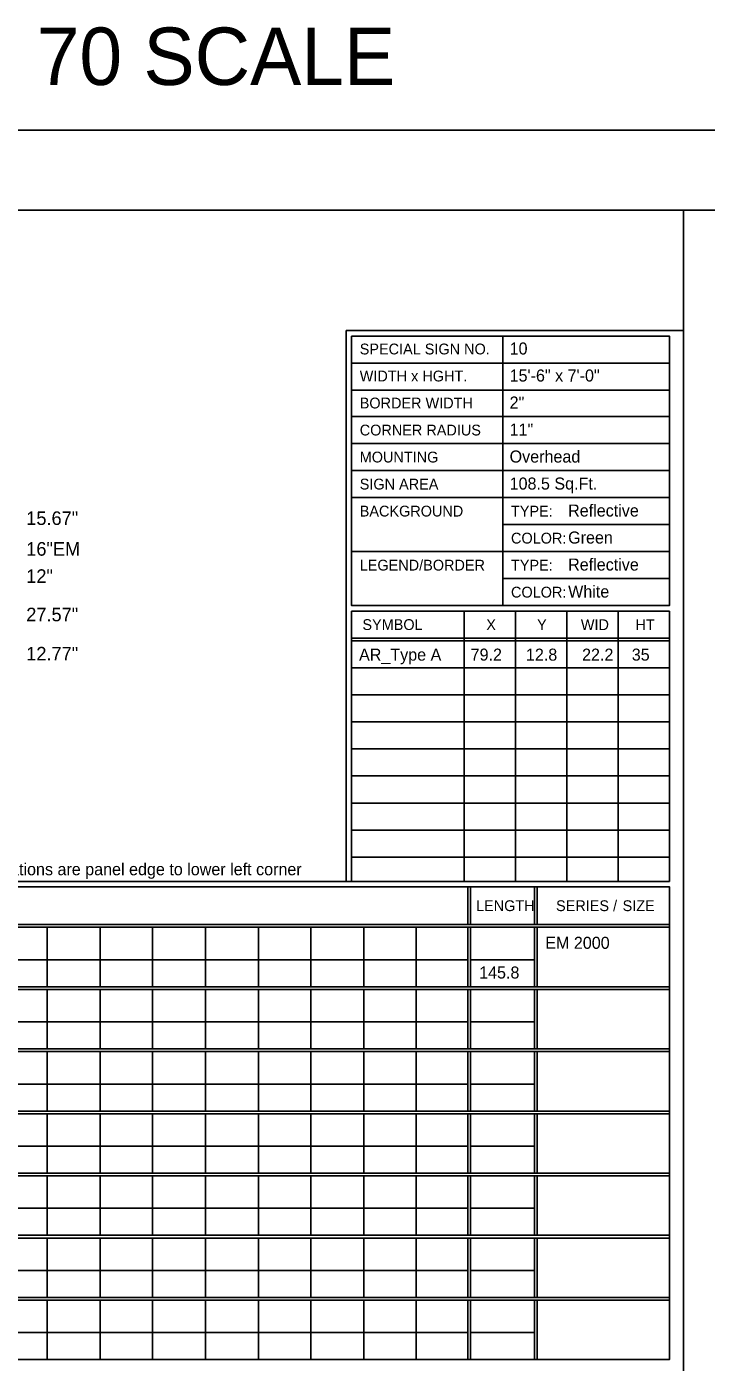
# Model space of a CAD drawing. Extents: x 2150010 to 2150174, y 145114 to 145224.
# Drawn here: x 2150107.3 to 2150136.4, y 145167.1 to 145224.4 of the extents above; entities that cross this region are included whole.
import ezdxf

# ---------------------------------------------------------------- set-up
doc = ezdxf.new("R2010")
doc.units = 0
for name, color, linetype in [('BORDER', 7, 'Continuous'), ('GSDIMS', 7, 'Continuous'), ('GSSHT', 7, 'Continuous'), ('Level 1', 7, 'Continuous'), ('PDF', 7, 'Continuous'), ('TEXT', 7, 'Continuous')]:
    doc.layers.add(name, color=color, linetype=linetype)

msp = doc.modelspace()

# ---------------------------------------------------------------- linework, layer by layer
at = {"layer": 'BORDER'}
for p, q in [((2150010.458, 145219.948), (2150174.061, 145219.948)), ((2150171.536, 145216.512), (2150017.557, 145216.512))]:
    msp.add_line(p, q, dxfattribs=at)
at = {"layer": 'Level 1'}
for p, q in [((2150135.447, 145216.512), (2150135.447, 145124.606)), ((2150120.969, 145211.34), (2150135.447, 145211.34)), ((2150127.694, 145211.108), (2150127.694, 145199.537)), ((2150121.201, 145209.949), (2150134.843, 145209.949)), ((2150121.201, 145208.789), (2150134.843, 145208.789)), ((2150121.201, 145207.653), (2150134.843, 145207.653)), ((2150121.201, 145206.494), (2150134.843, 145206.494)), ((2150121.201, 145205.334), (2150134.843, 145205.334)), ((2150121.201, 145204.175), (2150134.843, 145204.175)), ((2150127.694, 145203.015), (2150134.843, 145203.015)), ((2150121.201, 145201.856), (2150134.843, 145201.856)), ((2150127.694, 145200.696), (2150134.843, 145200.696)), ((2150121.201, 145187.705), (2150121.201, 145199.305)), ((2150121.201, 145199.305), (2150134.843, 145199.305)), ((2150126.031, 145199.299), (2150126.031, 145198.14)), ((2150128.234, 145199.299), (2150128.234, 145198.14)), ((2150130.437, 145199.299), (2150130.437, 145198.14)), ((2150132.64, 145199.299), (2150132.64, 145198.14)), ((2150134.843, 145199.305), (2150134.843, 145187.705)), ((2150121.201, 145198.14), (2150134.843, 145198.14)), ((2150121.201, 145198.024), (2150134.843, 145198.024)), ((2150126.031, 145198.14), (2150126.031, 145187.705)), ((2150128.234, 145198.14), (2150128.234, 145187.705)), ((2150130.437, 145198.14), (2150130.437, 145187.705)), ((2150132.64, 145198.14), (2150132.64, 145187.705)), ((2150121.201, 145196.864), (2150134.843, 145196.864)), ((2150121.201, 145195.705), (2150134.843, 145195.705)), ((2150121.201, 145194.545), (2150134.843, 145194.545)), ((2150121.201, 145193.386), (2150134.843, 145193.386)), ((2150121.201, 145192.227), (2150134.843, 145192.227)), ((2150121.201, 145191.067), (2150134.843, 145191.067)), ((2150121.201, 145189.908), (2150134.843, 145189.908)), ((2150121.201, 145188.748), (2150134.843, 145188.748)), ((2150076.316, 145187.705), (2150121.342, 145187.705)), ((2150134.843, 145187.705), (2150121.201, 145187.705)), ((2150126.185, 145187.473), (2150126.185, 145185.849)), ((2150126.301, 145187.473), (2150126.301, 145185.849)), ((2150129.048, 145187.473), (2150129.048, 145185.849)), ((2150129.164, 145187.473), (2150129.164, 145185.849)), ((2150076.548, 145185.849), (2150134.843, 145185.849)), ((2150076.548, 145185.733), (2150134.843, 145185.733)), ((2150108.132, 145185.733), (2150108.132, 145183.183)), ((2150110.405, 145185.733), (2150110.405, 145183.183)), ((2150112.654, 145185.733), (2150112.654, 145183.183)), ((2150114.927, 145185.733), (2150114.927, 145183.183)), ((2150117.199, 145185.733), (2150117.199, 145183.183)), ((2150119.449, 145185.733), (2150119.449, 145183.183)), ((2150121.721, 145185.733), (2150121.721, 145183.183)), ((2150123.97, 145185.733), (2150123.97, 145183.183)), ((2150126.185, 145185.733), (2150126.185, 145183.183)), ((2150126.301, 145185.733), (2150126.301, 145183.183)), ((2150129.048, 145185.733), (2150129.048, 145183.183)), ((2150129.164, 145185.733), (2150129.164, 145183.183)), ((2150076.548, 145184.342), (2150126.185, 145184.342)), ((2150126.301, 145184.342), (2150129.048, 145184.342)), ((2150076.548, 145183.183), (2150134.843, 145183.183)), ((2150076.548, 145183.067), (2150134.843, 145183.067)), ((2150108.132, 145183.067), (2150108.132, 145180.516)), ((2150110.405, 145183.067), (2150110.405, 145180.516)), ((2150112.654, 145183.067), (2150112.654, 145180.516)), ((2150114.927, 145183.067), (2150114.927, 145180.516)), ((2150117.199, 145183.067), (2150117.199, 145180.516)), ((2150119.449, 145183.067), (2150119.449, 145180.516)), ((2150121.721, 145183.067), (2150121.721, 145180.516)), ((2150123.97, 145183.067), (2150123.97, 145180.516)), ((2150126.185, 145183.067), (2150126.185, 145180.516)), ((2150126.301, 145183.067), (2150126.301, 145180.516)), ((2150129.048, 145183.067), (2150129.048, 145180.516)), ((2150129.164, 145183.067), (2150129.164, 145180.516)), ((2150076.548, 145181.675), (2150126.185, 145181.675)), ((2150126.301, 145181.675), (2150129.048, 145181.675)), ((2150076.548, 145180.516), (2150134.843, 145180.516)), ((2150076.548, 145180.4), (2150134.843, 145180.4)), ((2150108.132, 145180.4), (2150108.132, 145177.849)), ((2150110.405, 145180.4), (2150110.405, 145177.849)), ((2150112.654, 145180.4), (2150112.654, 145177.849)), ((2150114.927, 145180.4), (2150114.927, 145177.849)), ((2150117.199, 145180.4), (2150117.199, 145177.849)), ((2150119.449, 145180.4), (2150119.449, 145177.849)), ((2150121.721, 145180.4), (2150121.721, 145177.849)), ((2150123.97, 145180.4), (2150123.97, 145177.849)), ((2150126.185, 145180.4), (2150126.185, 145177.849)), ((2150126.301, 145180.4), (2150126.301, 145177.849)), ((2150129.048, 145180.4), (2150129.048, 145177.849)), ((2150129.164, 145180.4), (2150129.164, 145177.849)), ((2150076.548, 145179.008), (2150126.185, 145179.008)), ((2150126.301, 145179.008), (2150129.048, 145179.008)), ((2150076.548, 145177.849), (2150134.843, 145177.849)), ((2150076.548, 145177.733), (2150134.843, 145177.733)), ((2150108.132, 145177.733), (2150108.132, 145175.182)), ((2150110.405, 145177.733), (2150110.405, 145175.182)), ((2150112.654, 145177.733), (2150112.654, 145175.182)), ((2150114.927, 145177.733), (2150114.927, 145175.182)), ((2150117.199, 145177.733), (2150117.199, 145175.182)), ((2150119.449, 145177.733), (2150119.449, 145175.182)), ((2150121.721, 145177.733), (2150121.721, 145175.182)), ((2150123.97, 145177.733), (2150123.97, 145175.182)), ((2150126.185, 145177.733), (2150126.185, 145175.182)), ((2150126.301, 145177.733), (2150126.301, 145175.182)), ((2150129.048, 145177.733), (2150129.048, 145175.182)), ((2150129.164, 145177.733), (2150129.164, 145175.182)), ((2150076.548, 145176.342), (2150126.185, 145176.342)), ((2150126.301, 145176.342), (2150129.048, 145176.342)), ((2150076.548, 145175.182), (2150134.843, 145175.182)), ((2150076.548, 145175.066), (2150134.843, 145175.066)), ((2150108.132, 145175.066), (2150108.132, 145172.515)), ((2150110.405, 145175.066), (2150110.405, 145172.515)), ((2150112.654, 145175.066), (2150112.654, 145172.515)), ((2150114.927, 145175.066), (2150114.927, 145172.515)), ((2150117.199, 145175.066), (2150117.199, 145172.515)), ((2150119.449, 145175.066), (2150119.449, 145172.515)), ((2150121.721, 145175.066), (2150121.721, 145172.515)), ((2150123.97, 145175.066), (2150123.97, 145172.515)), ((2150126.185, 145175.066), (2150126.185, 145172.515)), ((2150126.301, 145175.066), (2150126.301, 145172.515)), ((2150129.048, 145175.066), (2150129.048, 145172.515)), ((2150129.164, 145175.066), (2150129.164, 145172.515)), ((2150076.548, 145173.675), (2150126.185, 145173.675)), ((2150126.301, 145173.675), (2150129.048, 145173.675)), ((2150076.548, 145172.515), (2150134.843, 145172.515)), ((2150076.548, 145172.399), (2150134.843, 145172.399)), ((2150108.132, 145172.399), (2150108.132, 145169.849)), ((2150110.405, 145172.399), (2150110.405, 145169.849)), ((2150112.654, 145172.399), (2150112.654, 145169.849)), ((2150114.927, 145172.399), (2150114.927, 145169.849)), ((2150117.199, 145172.399), (2150117.199, 145169.849)), ((2150119.449, 145172.399), (2150119.449, 145169.849)), ((2150121.721, 145172.399), (2150121.721, 145169.849)), ((2150123.97, 145172.399), (2150123.97, 145169.849)), ((2150126.185, 145172.399), (2150126.185, 145169.849)), ((2150126.301, 145172.399), (2150126.301, 145169.849)), ((2150129.048, 145172.399), (2150129.048, 145169.849)), ((2150129.164, 145172.399), (2150129.164, 145169.849)), ((2150076.548, 145171.008), (2150126.185, 145171.008)), ((2150126.301, 145171.008), (2150129.048, 145171.008)), ((2150076.548, 145169.849), (2150134.843, 145169.849)), ((2150076.548, 145169.733), (2150134.843, 145169.733)), ((2150108.132, 145169.733), (2150108.132, 145167.182)), ((2150110.405, 145169.733), (2150110.405, 145167.182)), ((2150112.654, 145169.733), (2150112.654, 145167.182)), ((2150114.927, 145169.733), (2150114.927, 145167.182)), ((2150117.199, 145169.733), (2150117.199, 145167.182)), ((2150119.449, 145169.733), (2150119.449, 145167.182)), ((2150121.721, 145169.733), (2150121.721, 145167.182)), ((2150123.97, 145169.733), (2150123.97, 145167.182)), ((2150126.185, 145169.733), (2150126.185, 145167.182)), ((2150126.301, 145169.733), (2150126.301, 145167.182)), ((2150129.048, 145169.733), (2150129.048, 145167.182)), ((2150129.164, 145169.733), (2150129.164, 145167.182)), ((2150076.548, 145168.341), (2150126.185, 145168.341)), ((2150126.301, 145168.341), (2150129.048, 145168.341))]:
    msp.add_line(p, q, dxfattribs=at)
msp.add_lwpolyline([(2150120.969, 145187.705), (2150120.969, 145211.34)], dxfattribs=at)
for points in [[(2150121.201, 145211.108), (2150134.843, 145211.108), (2150134.843, 145199.537), (2150121.201, 145199.537)], [(2150076.548, 145187.473), (2150134.843, 145187.473), (2150134.843, 145167.182), (2150076.548, 145167.182)]]:
    msp.add_lwpolyline(points, close=True, dxfattribs=at)
at = {"layer": 'PDF'}
msp.add_lwpolyline([(2150010.458, 145114.088), (2150174.061, 145114.088), (2150174.061, 145219.948), (2150010.458, 145219.948)], close=True, dxfattribs=at)

# ---------------------------------------------------------------- texts
at = {"layer": 'GSDIMS'}
for s, p in [('15.67"', (2150107.237, 145203)), ('16"EM', (2150107.237, 145201.681)), ('12"', (2150107.237, 145200.514)), ('27.57"', (2150107.237, 145198.866)), ('12.77"', (2150107.237, 145197.185))]:
    msp.add_text(s, height=0.5833, dxfattribs=at).set_placement(p)
at = {"layer": 'GSSHT'}
for s, p in [('10', (2150127.983, 145210.315)), ('Overhead', (2150127.983, 145205.679))]:
    msp.add_text(s, height=0.5165, dxfattribs=at).set_placement(p)
at = {"layer": 'Level 1'}
for s, height, p in [('SPECIAL SIGN NO.', 0.46374, (2150121.549, 145210.32)), ('WIDTH x HGHT.', 0.46374, (2150121.549, 145209.16)), ('15\'-6" x 7\'-0"', 0.51652, (2150127.983, 145209.156)), ('BORDER WIDTH', 0.46374, (2150121.549, 145208.001)), ('2"', 0.5165, (2150127.983, 145207.997)), ('CORNER RADIUS', 0.46374, (2150121.549, 145206.841)), ('11"', 0.5165, (2150127.983, 145206.838)), ('MOUNTING', 0.4637, (2150121.549, 145205.682)), ('SIGN AREA', 0.4638, (2150121.549, 145204.522)), ('108.5 Sq.Ft.', 0.51652, (2150127.983, 145204.52)), ('BACKGROUND', 0.4637, (2150121.549, 145203.363)), ('TYPE:', 0.4637, (2150128.042, 145203.363)), ('Reflective', 0.5165, (2150130.494, 145203.362)), ('COLOR:', 0.4637, (2150128.042, 145202.203)), ('Green', 0.5165, (2150130.494, 145202.203)), ('LEGEND/BORDER', 0.46374, (2150121.549, 145201.044)), ('TYPE:', 0.4637, (2150128.042, 145201.044)), ('Reflective', 0.5165, (2150130.494, 145201.044)), ('COLOR:', 0.4637, (2150128.042, 145199.885)), ('White', 0.5165, (2150130.494, 145199.885)), ('SYMBOL', 0.4637, (2150121.665, 145198.493)), ('X', 0.464, (2150126.981, 145198.488)), ('Y', 0.464, (2150129.161, 145198.488)), ('WID', 0.4637, (2150131.04, 145198.488)), ('HT', 0.4637, (2150133.382, 145198.488)), ('AR_Type A', 0.5165, (2150121.52, 145197.177)), ('79.2', 0.5165, (2150126.31, 145197.177)), ('12.8', 0.5165, (2150128.683, 145197.177)), ('22.2', 0.5165, (2150131.092, 145197.177)), ('35', 0.5165, (2150133.225, 145197.177)), ('Letter locations are panel edge to lower left corner', 0.51652, (2150103.701, 145187.968)), ('LENGTH', 0.4638, (2150126.541, 145186.429)), ('LENGTH', 0.4638, (2150126.541, 145186.429)), ('SERIES /', 0.4638, (2150129.975, 145186.429)), ('SIZE', 0.4638, (2150132.832, 145186.429)), ('EM 2000', 0.5165, (2150129.512, 145184.81)), ('145.8', 0.5165, (2150126.674, 145183.535))]:
    msp.add_text(s, height=height, dxfattribs=at).set_placement(p)
at = {"layer": 'TEXT'}
msp.add_text('BORDER AND REPORT 70 SCALE', height=2.46401, dxfattribs=at).set_placement((2150070.157, 145221.883))

doc.saveas('drawing.dxf')
